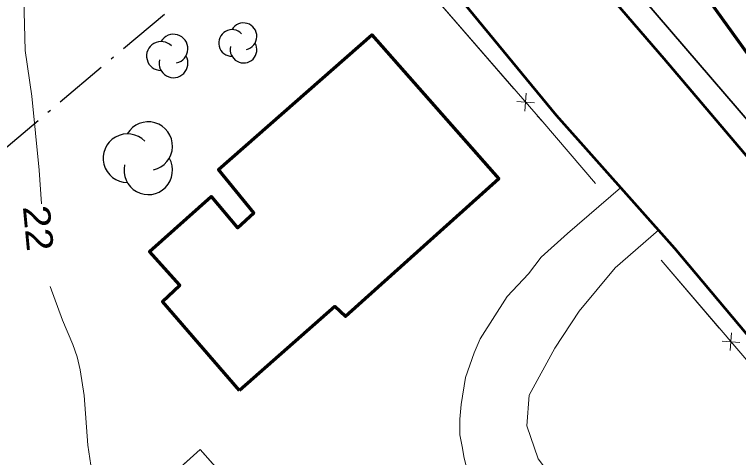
# Model space of a CAD drawing. Extents: x 356765 to 358572, y 5103174 to 5104650.
# Drawn here: x 357149.84 to 357190.38, y 5103881.41 to 5103906.19 of the extents above; entities that cross this region are included whole.
import ezdxf
from ezdxf.enums import TextEntityAlignment as Align

# ---------------------------------------------------------------- set-up
doc = ezdxf.new("R2010")
doc.units = 0
doc.header["$LTSCALE"] = 0.6
doc.linetypes.add('DOT_DASHED', pattern=[7.7, 5, -1.2, 0.3, -1.2])
for name, color, linetype, lineweight in [('19', 7, 'Continuous', 13), ('2', 7, 'Continuous', 13), ('21', 7, 'Continuous', 53), ('22', 7, 'Continuous', 35), ('31', 7, 'Continuous', 70), ('37', 7, 'Continuous', 13), ('41', 7, 'DOT_DASHED', 25), ('44', 7, 'Continuous', 25)]:
    doc.layers.add(name, color=color, linetype=linetype, lineweight=lineweight)

msp = doc.modelspace()

# ---------------------------------------------------------------- linework, layer by layer
at = {"layer": '19'}
for points in [[(357183.78, 5103896.49), (357180.8, 5103893.94), (357179.32, 5103892.61)], [(357185.45, 5103874.3), (357180.46, 5103879.62), (357179.16, 5103881.34), (357178.53, 5103883.18), (357178.65, 5103884.9), (357180.09, 5103887.53), (357181.46, 5103889.59), (357183.47, 5103892.01), (357185.9, 5103894.12)], [(357179.32, 5103892.61), (357178.62, 5103891.69), (357177.42, 5103890.42), (357175.91, 5103888.05), (357175.58, 5103887.27), (357175.1, 5103885.89), (357174.84, 5103884.38), (357174.77, 5103883.55), (357174.77, 5103882.67), (357174.9, 5103882.02), (357175.02, 5103881.37), (357175.34, 5103880.13)]]:
    msp.add_lwpolyline(points, dxfattribs=at)
at = {"layer": '2'}
for points in [[(357151.34, 5103895.59), (357151.22, 5103897.48), (357150.8, 5103901.62), (357150.43, 5103904.18), (357150.29, 5103909.98), (357150.5, 5103913.51), (357150.52, 5103916.22), (357150.62, 5103916.88), (357150.79, 5103917.48), (357151.83, 5103919.45), (357152.03, 5103919.92), (357152.07, 5103920.4), (357151.88, 5103920.88), (357151.58, 5103921.4), (357151.21, 5103921.86)], [(357154.23, 5103880.23), (357153.95, 5103882.09), (357153.73, 5103884.87), (357153.52, 5103886.32), (357153.34, 5103887.03), (357153.1, 5103887.73), (357152.53, 5103889.09), (357151.83, 5103890.98)]]:
    msp.add_lwpolyline(points, dxfattribs=at)
at = {"layer": '21'}
for points in [[(357166.88, 5103926.08), (357186.19, 5103903.73), (357197.29, 5103890.67), (357216.18, 5103868.59), (357219.79, 5103864.45), (357221.65, 5103864.59), (357224.2, 5103865.18), (357226.48, 5103866.46), (357228.18, 5103868.68), (357228.77, 5103870.4), (357229.42, 5103873.87), (357230.17, 5103877.87), (357230.45, 5103879.13), (357232.13, 5103887.4), (357233.82, 5103895.66), (357235, 5103902.34), (357236.8, 5103914.18)], [(357175.01, 5103906.8), (357180.17, 5103900.55), (357186.79, 5103893.12), (357193.64, 5103884.97), (357199.42, 5103878.25), (357202.11, 5103875.23), (357182.66, 5103859.79), (357173.28, 5103851.91), (357167.64, 5103847.28)]]:
    msp.add_lwpolyline(points, dxfattribs=at)
at = {"layer": '22'}
msp.add_lwpolyline([(357221.36, 5103864.57), (357203.17, 5103886.01), (357184.34, 5103907.9), (357170.96, 5103923.59), (357161.12, 5103935.05), (357158.11, 5103938.34), (357149.98, 5103947.63), (357129.46, 5103972.34), (357111.79, 5103992.65), (357092.35, 5104015.36), (357072.16, 5104038.84), (357054.59, 5104060.46), (357032.27, 5104090.76), (357019.29, 5104110.68), (357013.99, 5104119.24)], dxfattribs=at)
at = {"layer": '31'}
for points in [[(357196.18, 5103915.8), (357201.33, 5103908.97), (357197.88, 5103906.29), (357199.11, 5103904.69), (357195.86, 5103902.07), (357194.28, 5103904.05), (357192.11, 5103902.3), (357186.48, 5103910.12), (357193.19, 5103915.11), (357194, 5103914.11), (357196.18, 5103915.8)], [(357162.44, 5103885.16), (357158.12, 5103890.13), (357159.1, 5103891.04), (357157.39, 5103892.94), (357160.85, 5103896.01), (357162.33, 5103894.26), (357163.23, 5103895.09), (357161.26, 5103897.51), (357169.84, 5103905.05), (357176.96, 5103897), (357168.37, 5103889.3), (357167.78, 5103889.86), (357162.44, 5103885.16)]]:
    msp.add_lwpolyline(points, close=True, dxfattribs=at)
at = {"layer": '37'}
for p, q in [((357174.52, 5103905.82), (357171.24, 5103909.59)), ((357177.8, 5103902.04), (357174.52, 5103905.82)), ((357178.49, 5103901.79), (357178.42, 5103900.79)), ((357178.96, 5103901.25), (357177.96, 5103901.32)), ((357186.05, 5103892.44), (357189.3, 5103888.64)), ((357189.92, 5103887.39), (357189.99, 5103888.38)), ((357189.46, 5103887.92), (357190.45, 5103887.85))]:
    msp.add_line(p, q, dxfattribs=at)
for points in [[(357182.37, 5103896.74), (357179.42, 5103900.18), (357167.47, 5103913.92)], [(357182.37, 5103896.74), (357179.42, 5103900.18), (357179.11, 5103900.53)], [(357186.05, 5103892.44), (357200.9, 5103875.12), (357198.46, 5103872.84), (357180.35, 5103858.53), (357167.68, 5103873.22), (357161.24, 5103880.71), (357160.24, 5103881.86), (357147.14, 5103870.09), (357146.92, 5103870.1), (357145.06, 5103870.17), (357133.97, 5103871.46), (357125.77, 5103882.5), (357113.98, 5103897.79)], [(357160.92, 5103881.08), (357160.24, 5103881.86), (357157.29, 5103879.21)]]:
    msp.add_lwpolyline(points, dxfattribs=at)
at = {"layer": '41'}
msp.add_lwpolyline([(357128.32, 5103881.6), (357138.26, 5103889.41), (357166.02, 5103912.77)], dxfattribs=at)
at = {"layer": '44'}
for centre, radius, start, end in [((357162.6617, 5103904.97), 0.7462, 282.26917, 149.72626), ((357162.0199, 5103904.5969), 0.7462, 44.11537, 269.80396), ((357158.7382, 5103904.2733), 0.8098, 282.26917, 149.72626), ((357158.0418, 5103903.8684), 0.8098, 44.11537, 269.80396), ((357162.6617, 5103904.2239), 0.7462, 166.93686, 29.62122), ((357158.7382, 5103903.4635), 0.8098, 166.93686, 29.62122), ((357157.327, 5103898.8296), 1.3576, 282.26917, 149.72626), ((357156.1595, 5103898.1508), 1.3576, 44.11537, 269.80396), ((357157.327, 5103897.472), 1.3576, 166.93686, 29.62122)]:
    msp.add_arc(centre, radius, start, end, dxfattribs=at)

# ---------------------------------------------------------------- texts
at = {"layer": '2', "width": 1.15}
msp.add_text('22', height=1.5, rotation=275.447, dxfattribs=at).set_placement((357150.4234, 5103894.1662), align=Align.CENTER)

doc.saveas('drawing.dxf')
